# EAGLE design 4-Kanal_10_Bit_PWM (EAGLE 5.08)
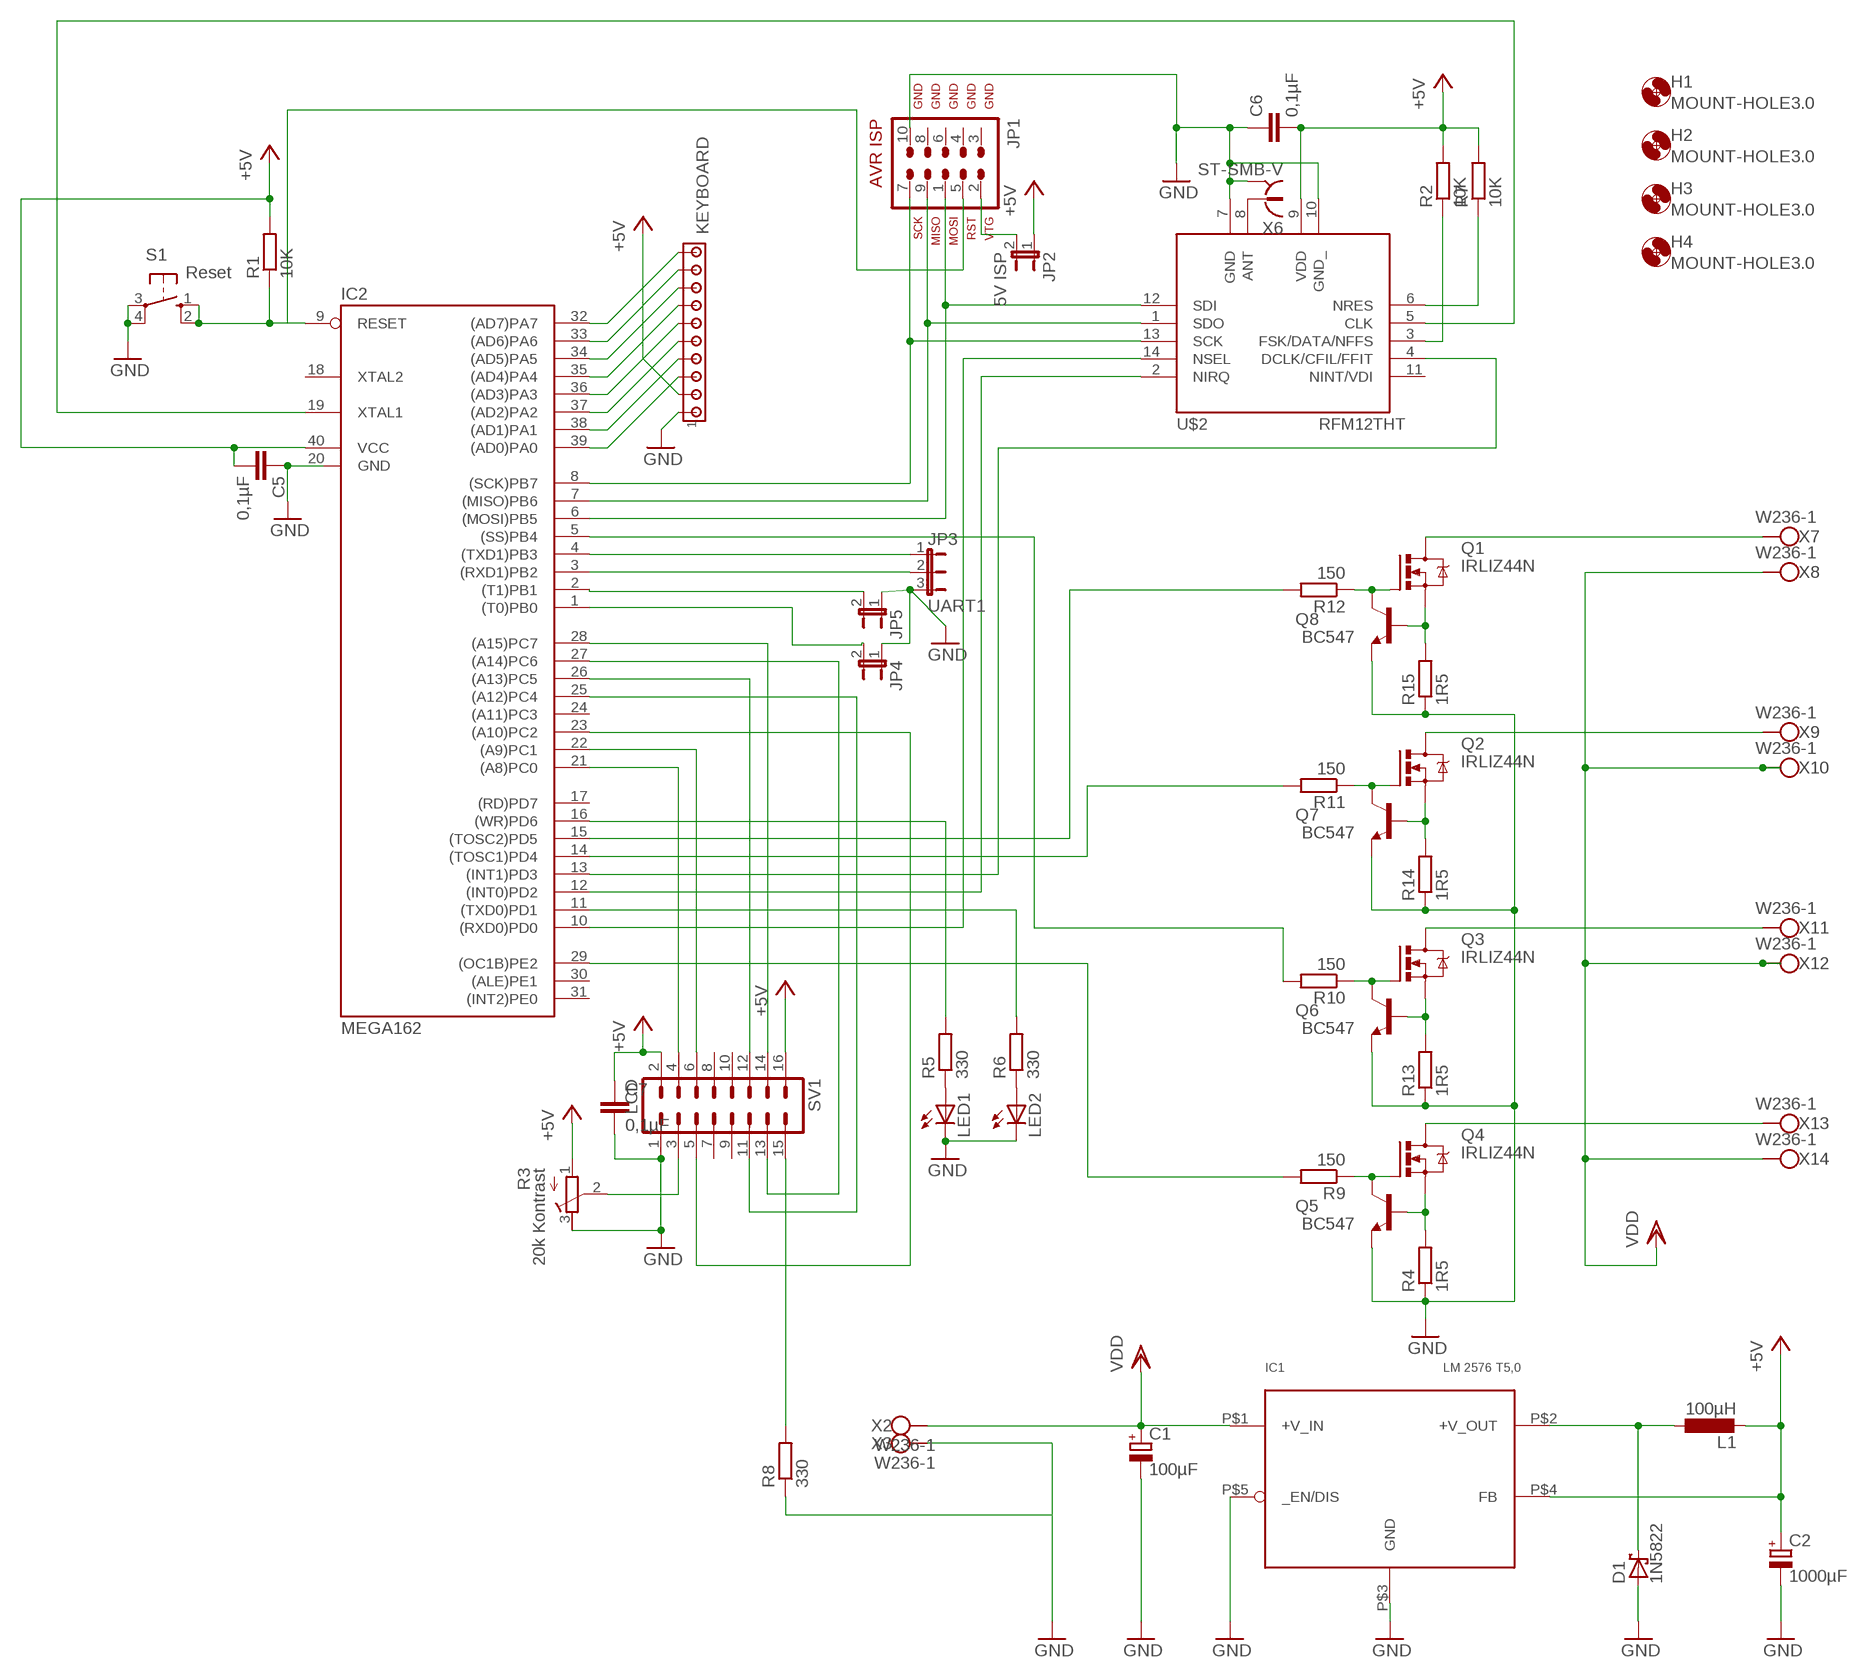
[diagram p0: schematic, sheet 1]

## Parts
C1  100µF  CPOL-EUE5-10.5  [E5-10,5]
C2  1000µF  CPOL-EUE5-10.5  [E5-10,5]
C5  0,1µF  C-EUC1812  [C1812]
C6  0,1µF  C-EUC1812  [C1812]
C7  0,1µF  C-EUC1812  [C1812]
D1  1N5822  1N5908  [C4111-15]
H1  MOUNT-HOLE3.0  [3,0]
H2  MOUNT-HOLE3.0  [3,0]
H3  MOUNT-HOLE3.0  [3,0]
H4  MOUNT-HOLE3.0  [3,0]
IC1  LM 2576 T5,0  LM2576-T05D  [TO220-5_STAGGERED]
IC2  MEGA162  MEGA161LP  [DIL40]
JP1  AVR-ISP  AVR-ISP-10ML10  [ML10]
JP2  5V ISP  JP1E  [JP1]
JP3  UART1  JP2E  [JP2]
JP4  JP1E  [JP1]
JP5  JP1E  [JP1]
KEYBOARD  MTA10-100  [10X10MTA]
L1  100µH  L-EUTJ4-U1  [TJ4-U1]
LED1  LED5MM  [LED5MM]
LED2  LED5MM  [LED5MM]
Q1  IRLIZ44N  STP5NA50  [TO220BV]
Q2  IRLIZ44N  STP5NA50  [TO220BV]
Q3  IRLIZ44N  STP5NA50  [TO220BV]
Q4  IRLIZ44N  STP5NA50  [TO220BV]
Q5  BC547  2N5088  [TO92]
Q6  BC547  2N5088  [TO92]
Q7  BC547  2N5088  [TO92]
Q8  BC547  2N5088  [TO92]
R1  10K  R-EU_0207/7  [0207/7]
R2  10K  R-EU_0207/10  [0207/10]
R3  20k Kontrast  R-TRIMM64W  [RTRIM64W]
R4  1R5  R-EU_0207/7  [0207/7]
R5  330  R-EU_0207/7  [0207/7]
R6  330  R-EU_0207/7  [0207/7]
R7  10K  R-EU_0207/7  [0207/7]
R8  330  R-EU_0207/7  [0207/7]
R9  150  R-EU_0207/7  [0207/7]
R10  150  R-EU_0207/7  [0207/7]
R11  150  R-EU_0207/7  [0207/7]
R12  150  R-EU_0207/7  [0207/7]
R13  1R5  R-EU_0207/7  [0207/7]
R14  1R5  R-EU_0207/7  [0207/7]
R15  1R5  R-EU_0207/7  [0207/7]
S1  Reset  10-XX  [B3F-10XX]
SV1  LCD  ML16  [ML16]
U$2  RFM12THT  [RFM12]
X2  W236-1  [W236-1]
X3  W236-1  [W236-1]
X6  ST-SMB-V  [ST-SMB-V]
X7  W236-1  [W236-1]
X8  W236-1  [W236-1]
X9  W236-1  [W236-1]
X10  W236-1  [W236-1]
X11  W236-1  [W236-1]
X12  W236-1  [W236-1]
X13  W236-1  [W236-1]
X14  W236-1  [W236-1]

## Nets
+5V: C2.+ C5.2 C6.2 C7.1 IC1.P$4(FB) IC2.40(VCC) JP2.1 KEYBOARD.2 L1.2 R1.2 R2.2 R3.1(E) R7.2 SV1.2 SV1.16 U$2.9(VDD)
GND: C1.- C2.- C5.1 C6.1 C7.2 D1.A IC1.P$3(GND) IC1.P$5(_EN/DIS) JP1.10 JP3.3 JP4.1 JP5.1 KEYBOARD.1 LED1.K(C) LED2.K(C) Q5.3(E) Q6.3(E) Q7.3(E) Q8.3(E) R3.3(A) R4.1 R8.1 R13.1 R14.1 R15.1 S1.3(P) S1.4(P1) SV1.1 U$2.7(GND) U$2.10(GND_) X3.1(KL1) X6.2(GND)
N$1: IC2.39((AD0)PA0) KEYBOARD.3
N$2: D1.C IC1.P$2(+V_OUT) L1.1
N$3: Q1.D X7.1(KL1)
N$4: IC2.5((SS)PB4) R10.2
N$5: IC2.29((OC1B)PE2) R9.2
N$6: IC2.14((TOSC1)PD4) R11.2
N$7: Q2.D X9.1(KL1)
N$8: Q3.D X11.1(KL1)
N$9: Q4.D X13.1(KL1)
N$10: IC2.9(RESET) JP1.5 R1.1 S1.1(S) S1.2(S1)
N$11: IC2.12((INT0)PD2) U$2.2(NIRQ)
N$12: Q4.G Q5.1(C) R9.1
N$13: Q3.G Q6.1(C) R10.1
N$15: Q1.G Q8.1(C) R12.1
N$16: IC2.13((INT1)PD3) U$2.4(DCLK/CFIL/FFIT)
N$17: IC2.6((MOSI)PB5) JP1.1 U$2.12(SDI)
N$18: IC2.7((MISO)PB6) JP1.9 U$2.1(SDO)
N$19: IC2.8((SCK)PB7) JP1.7 U$2.13(SCK)
N$20: IC2.38((AD1)PA1) KEYBOARD.4
N$21: IC2.19(XTAL1) U$2.5(CLK)
N$22: R2.1 U$2.3(FSK/DATA/NFFS)
N$23: IC2.37((AD2)PA2) KEYBOARD.5
N$24: IC2.10((RXD0)PD0) U$2.14(NSEL)
N$25: JP1.2 JP2.2
N$26: IC2.36((AD3)PA3) KEYBOARD.6
N$27: IC2.35((AD4)PA4) KEYBOARD.7
N$28: IC2.34((AD5)PA5) KEYBOARD.8
N$29: IC2.33((AD6)PA6) KEYBOARD.9
N$30: IC2.32((AD7)PA7) KEYBOARD.10
N$31: IC2.4((TXD1)PB3) JP3.1
N$32: R3.2(S) SV1.3
N$34: IC2.28((A15)PC7) SV1.14
N$35: IC2.26((A13)PC5) SV1.12
N$36: IC2.21((A8)PC0) SV1.4
N$37: IC2.22((A9)PC1) SV1.6
N$38: IC2.27((A14)PC6) SV1.13
N$39: IC2.25((A12)PC4) SV1.11
N$40: Q4.S Q5.2(B) R4.2
N$41: Q2.G Q7.1(C) R11.1
N$42: Q3.S Q6.2(B) R13.2
N$43: Q2.S Q7.2(B) R14.2
N$44: IC2.23((A10)PC2) SV1.5
N$45: U$2.8(ANT) X6.1
N$46: IC2.15((TOSC2)PD5) R12.2
N$47: LED1.A R5.1
N$48: IC2.16((WR)PD6) R5.2
N$49: IC2.3((RXD1)PB2) JP3.2
N$50: LED2.A R6.1
N$51: IC2.11((TXD0)PD1) R6.2
N$52: IC2.1((T0)PB0) JP4.2
N$53: IC2.2((T1)PB1) JP5.2
N$55: R7.1 U$2.6(NRES)
N$56: Q1.S Q8.2(B) R15.2
N$75: R8.2 SV1.15
VDD: C1.+ IC1.P$1(+V_IN) X2.1(KL1) X8.1(KL1) X10.1(KL1) X10.2(KL2) X12.1(KL1) X12.2(KL2) X14.1(KL1)
Unconnected: IC2.17((RD)PD7) IC2.18(XTAL2) IC2.24((A11)PC3) IC2.30((ALE)PE1) IC2.31((INT2)PE0) JP1.3 JP1.4 JP1.6 JP1.8 SV1.7 SV1.8 SV1.9 SV1.10 U$2.11(NINT/VDI) X2.2(KL2) X3.2(KL2) X7.2(KL2) X8.2(KL2) X9.2(KL2) X11.2(KL2) X13.2(KL2) X14.2(KL2)

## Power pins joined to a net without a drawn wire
GND: IC2.20(GND) X6.3(GND) X6.4(GND) X6.5(GND)

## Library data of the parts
C1 C2 = rcl:CPOL-EU: POLARIZED CAPACITOR, European symbol
C5-C7 = rcl:C-EU: CAPACITOR, European symbol
D1 = diode:1N5908: DIODE
H1-H4 = holes:MOUNT-HOLE: MOUNTING HOLE with drill center marker
IC1 = to220-custom:LM2576-T05D: LM2576/LM2576HV Series SIMPLE SWITCHER® 3A Step-Down Voltage Regulator STAGGERED PACKAGE
IC2 = atmel:MEGA161*P: MICROCONTROLLER 16 Kbytes FLASH 512 bytes EEPROM 1 Kbytes SRAM dual UART hardware multiplier Source: avr.lbr
JP1 = uwegw_eagle_lib:AVR-ISP-10: AVR ISP-10 Serial Programming Header
JP2 JP4 JP5 = jumper:JP1E: JUMPER
JP3 = jumper:JP2E: JUMPER
KEYBOARD = con-amp:MTA10-100: AMP connector
L1 = rcl:L-EU: INDUCTOR, European symbol
LED1 LED2 = led:LED: LED
Q1-Q4 = transistor-power:STP5NA50: N-CHANNEL MOS FET
Q5-Q8 = transistor-npn:2N5088: NPN Transistor
R1 R2 R4-R15 = rcl:R-EU_: RESISTOR, European symbol
R3 = rcl:R-TRIMM: Trimm resistor
S1 = switch-omron:10-XX: OMRON SWITCH
SV1 = con-harting-ml:ML16: HARTING
U$2 = uwegw_eagle_lib:RFM12: RFM12 Funkmodul SPI-Schnittstelle 433MHz Pollin Nr. 810049
X2 X3 X7-X14 = con-wago-508:W236-1: WAGO SREW CLAMP
X6 = con-coax:ST-SMB-V: MALE SMB CONNECTOR Radiall distributor RS 193-8855G7

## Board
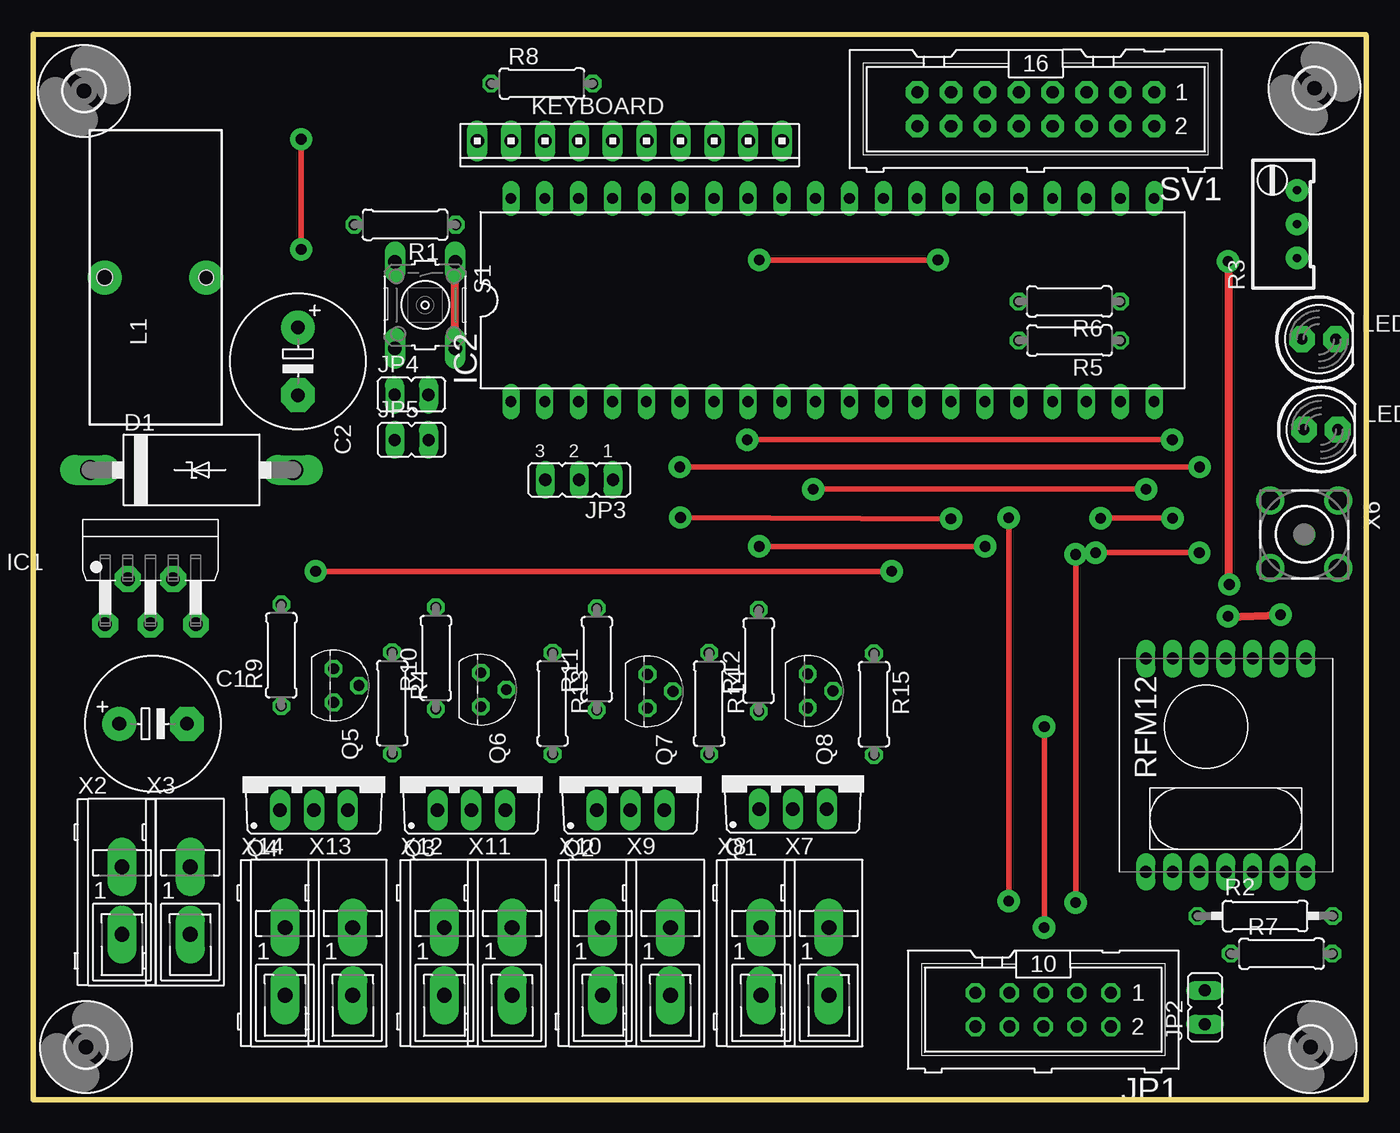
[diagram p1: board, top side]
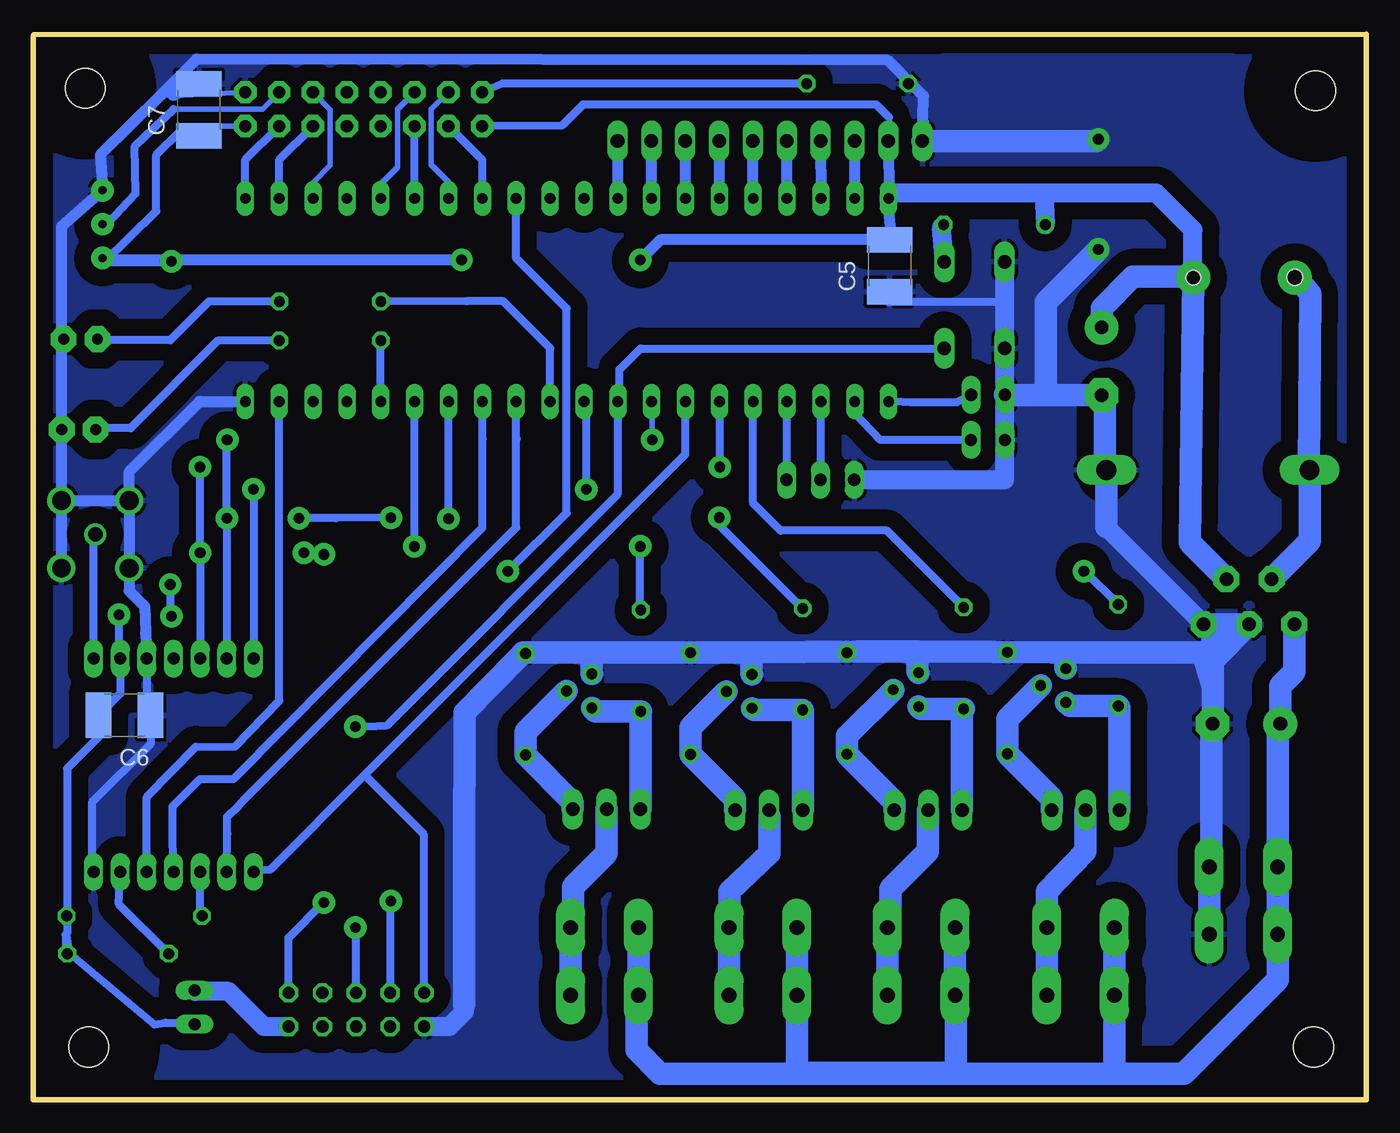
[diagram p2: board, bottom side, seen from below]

Size 100 x 80 mm. Coordinates in mm from the lower left corner, seen from the top.
Outline: 100,79.8 100,0 0,0 0,79.94
Outline: 0,80 0,79.94
Outline: 0,79.94 99.98,79.89
Copper layers (1*16): Top 0.035mm / dielectric 1.5mm / Bottom 0.035mm
Design rules "default": minimum track width 10mil, minimum drill 24mil, track to track 8mil, track to pad 8mil, pad to pad 8mil, via to via 8mil, smd to smd 8mil, copper to edge 40mil, drill to drill 8mil, minimum pad ring 10mil, minimum via ring 8mil, stop-mask expansion 4mil, vias tented up to drill 0mil, thermal gap 10mil

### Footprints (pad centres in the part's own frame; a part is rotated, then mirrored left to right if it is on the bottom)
E5-10,5 = drill 1.016 pad 2.54 round: + -2.54,0 | drill 1.016 pad 2.54 octagon: - 2.54,0
C1812 = smd 1.9 x 3.4: 1 -1.95,0; 2 1.95,0
C4111-15 = drill 1.499 long: A 7.62,0; C -7.62,0
3,0 = hole 3: 0,0
TO220-5_STAGGERED = drill 1.016 pad 1.93 octagon: P$1 -3.404,-3.404; P$2 -1.702,0; P$3 0,-3.404; P$4 1.702,0; P$5 3.404,-3.404
DIL40 = drill 0.813 long: 1 -24.13,-7.62; 2 -21.59,-7.62; 3 -19.05,-7.62; 4 -16.51,-7.62; 5 -13.97,-7.62; 6 -11.43,-7.62; 7 -8.89,-7.62; 8 -6.35,-7.62; 9 -3.81,-7.62; 10 -1.27,-7.62; 11 1.27,-7.62; 12 3.81,-7.62; 13 6.35,-7.62; 14 8.89,-7.62; 15 11.43,-7.62; 16 13.97,-7.62; 17 16.51,-7.62; 18 19.05,-7.62; 19 21.59,-7.62; 20 24.13,-7.62; 21 24.13,7.62; 22 21.59,7.62; 23 19.05,7.62; 24 16.51,7.62; 25 13.97,7.62; 26 11.43,7.62; 27 8.89,7.62; 28 6.35,7.62; 29 3.81,7.62; 30 1.27,7.62; 31 -1.27,7.62; 32 -3.81,7.62; 33 -6.35,7.62; 34 -8.89,7.62; 35 -11.43,7.62; 36 -13.97,7.62; 37 -16.51,7.62; 38 -19.05,7.62; 39 -21.59,7.62; 40 -24.13,7.62
ML10 = drill 0.914 octagon: 1 -5.08,-1.27; 2 -5.08,1.27; 3 -2.54,-1.27; 4 -2.54,1.27; 5 0,-1.27; 6 0,1.27; 7 2.54,-1.27; 8 2.54,1.27; 9 5.08,-1.27; 10 5.08,1.27
JP1 = drill 0.914 long: 1 0,-1.27; 2 0,1.27
JP2 = drill 0.914 long: 1 -2.54,0; 2 0,0; 3 2.54,0
10X10MTA = drill 1.016 long: 1 11.43,0; 2 8.89,0; 3 6.35,0; 4 3.81,0; 5 1.27,0; 6 -1.27,0; 7 -3.81,0; 8 -6.35,0; 9 -8.89,0; 10 -11.43,0
TJ4-U1 = drill 0.9 pad 2.54 round: 1 -3.808,0; 2 3.808,0 | hole 1.2: -3.81,0 | hole 1.1: 3.81,0
LED5MM = drill 0.813 pad 1.93 octagon: A -1.27,0; K 1.27,0
TO220BV = drill 1.016 long: D 0,-2.54; G -2.54,-2.54; S 2.54,-2.54
TO92 = drill 0.813 octagon: 1 1.27,0; 2 0,1.905; 3 -1.27,0
0207/7 = drill 0.813 octagon: 1 -3.81,0; 2 3.81,0
0207/10 = drill 0.813 octagon: 1 -5.08,0; 2 5.08,0
RTRIM64W = drill 0.61 pad 1.676 round: 1 1.27,-2.54; 2 1.27,0; 3 1.27,2.54
B3F-10XX = drill 1.016 long: 1 -3.251,2.261; 2 3.251,2.261; 3 -3.251,-2.261; 4 3.251,-2.261
ML16 = drill 0.914 pad 1.676 octagon: 1 -8.89,-1.27; 2 -8.89,1.27; 3 -6.35,-1.27; 4 -6.35,1.27; 5 -3.81,-1.27; 6 -3.81,1.27; 7 -1.27,-1.27; 8 -1.27,1.27; 9 1.27,-1.27; 10 1.27,1.27; 11 3.81,-1.27; 12 3.81,1.27; 13 6.35,-1.27; 14 6.35,1.27; 15 8.89,-1.27; 16 8.89,1.27
RFM12 = drill 0.9 long: 1 -8,6; 2 -8,4; 3 -8,2; 4 -8,0; 5 -8,-2; 6 -8,-4; 7 -8,-6; 8 8,-6; 9 8,-4; 10 8,-2; 11 8,0; 12 8,2; 13 8,4; 14 8,6
W236-1 = drill 1.118 pad 2.184 long: 1 0,-2.54; 2 0,2.54
ST-SMB-V = drill 1.1 round: 1 0,0 | drill 1.4 round: 2 -2.54,2.54; 3 2.54,2.54; 4 2.54,-2.54; 5 -2.54,-2.54

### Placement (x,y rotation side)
C1  8.98,28.2 0 top
C2  19.85,55.39 270 top
C5  35.76,62.56 90 bottom
C6  93.16,28.83 180 bottom
C7  87.57,74.26 90 bottom
D1  11.87,47.24 0 top
H1  3.94,3.94 0 top
H2  95.84,3.94 0 top
H3  96.11,75.88 0 top
H4  3.81,75.69 0 top
IC1  8.79,39.05 0 top
IC2  59.96,59.99 0 top
JP1  75.77,6.74 180 top
JP2  87.9,6.92 0 top
JP3  40.95,46.5 180 top
JP4  28.37,52.88 270 top
JP5  28.38,49.49 270 top
KEYBOARD  44.74,71.92 180 top
L1  9.17,61.68 0 top
LED1  96.6,50.27 0 top
LED2  96.46,57.05 0 top
Q1  56.99,24.33 0 top
Q2  44.8,24.26 0 top
Q3  32.86,24.26 0 top
Q4  21.05,24.26 0 top
Q5  22.52,31.06 270 top
Q6  33.58,30.75 270 top
Q7  46.08,30.63 270 top
Q8  58.1,30.66 270 top
R1  27.89,65.64 180 top
R2  92.42,13.77 0 top
R3  93.54,65.68 0 top
R4  26.92,29.75 270 top
R5  77.74,56.95 180 top
R6  77.73,59.88 180 top
R7  93.65,10.94 0 top
R8  38.16,76.23 0 top
R9  18.6,33.33 90 top
R10  30.2,33.12 90 top
R11  42.28,33.04 90 top
R12  54.42,32.93 90 top
R13  38.96,29.72 270 top
R14  50.7,29.71 270 top
R15  63.07,29.66 270 top
S1  29.4,59.61 270 top
SV1  75.21,74.31 180 top
U$2  89.48,25.08 90 top
X2  6.65,14.92 0 top
X3  11.77,14.92 0 top
X6  95.35,42.41 270 top
X7  59.68,10.36 0 top
X8  54.6,10.36 0 top
X9  47.8,10.36 0 top
X10  42.72,10.36 0 top
X11  35.92,10.36 0 top
X12  30.84,10.36 0 top
X13  23.97,10.36 0 top
X14  18.89,10.36 0 top

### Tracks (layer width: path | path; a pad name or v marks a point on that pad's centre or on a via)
+5V  (via drill 0.8 pad 1.68)
  Top 0.406: v54.47,62.99 v67.87,62.99
  Top 0.61: v89.64,62.89 89.64,38.73 v89.73,38.64 | v89.64,36.27 89.73,36.37 89.57,36.21 v93.58,36.37
  Bottom 0.406: R7.2 97.58,10.84 R2.2 | SV1.2 88.21,73.03 88.21,72.71 | 35.78,73.67 35.78,71.99 KEYBOARD.2 | 88.21,72.71 88.21,72.35 C7.1 | C6.2 95.11,27.19 | 88.01,5.76 JP2.1 | 13.59,61.73 13,62.32 | 97.42,11.08 97.17,10.74 97.47,12.48 97.58,12.37 | R3.1 94.68,62.84 94.53,62.99 | 88.95,72.71 88.21,72.71
  Bottom 0.61: 35.75,67.69 IC2.40 35.83,66.67 | 35.67,64.83 35.67,63.91 C5.2 | C6.2 93.48,30.46 U$2.9 93.58,33.18 v93.58,36.37 | SV1.16 60.35,73.08 58.76,74.65 36.76,74.65 35.78,73.67 | 95.11,27.19 97.47,24.83 97.47,12.48 | 88.01,5.76 90.07,5.76 90.92,5.63 97.42,11.08 | 97.58,12.37 97.58,10.84 | 88.95,72.71 90.77,70.89 90.77,66.65 94.68,62.84 89.69,62.84 v89.64,62.89 | v89.73,38.64 89.73,36.43 89.76,36.4 v89.64,36.27
  Bottom 0.813: 35.75,67.69 KEYBOARD.2 | 35.83,66.67 35.67,64.83 | v67.87,62.99 94.53,62.99 | v54.47,62.99 52.95,64.51 C5.2
  Bottom 1.422: 13,62.32 13,65.26 15.76,68.02 19.21,68.02 | 19.21,68.02 35.42,68.02 IC2.40 | R1.2 24.2,67.99 19.21,68.02
  Bottom 1.676: IC1.P$4 13.24,41.8 L1.2 13.15,61.73 13.59,61.73 17.5,61.73 19.85,59.38 C2.+
GND  (via drill 0.8 pad 1.68)
  Top 0.406: v20.09,63.78 v20.09,72.06
  Bottom 0.406: 90.39,75.38 89.53,75.33 SV1.1 | 91.48,29.1 C6.1 | 95.61,17.21 U$2.7 | JP1.10 70.59,5.37 | 87.41,76.46 C7.2 | 27.1,63.5 27.14,63.54 | S1.4 27.14,58.4 27.13,58.41 | LED2.K 97.89,56.88 | LED1.K 97.87,50.35 97.89,50.37 | X6.5 92.79,44.98
  Bottom 0.61: JP5.1 27.21,50.42 JP4.1 27.13,58.41 27.09,59.85 | 27.09,59.85 27.1,63.5 | KEYBOARD.1 33.07,73.34 | C5.1 35.78,59.83 27.09,59.85 | 33.93,76.01 34.68,76.17 34.09,76.07 R8.1 | U$2.10 91.48,29.1 | C6.1 91.21,26.69 95.61,22.29 95.61,17.21 | 27.14,63.54 S1.3
  Bottom 0.813: KEYBOARD.1 33.21,75.29 33.93,76.01 35.89,77.97 87.76,78.07 90.39,75.38 94.97,70.89 R3.3 97.89,65.5 97.89,56.88 97.89,50.37 X6.2 | U$2.10 91.58,35 91.63,36.99 92.81,38.17 X6.4 X6.5 X6.2 | X6.2 X6.3 | 89.53,75.33 87.41,76.46 | IC2.20 87.53,52.37 92.79,47.12 92.79,44.98 | 67.67,19.62 67.67,17.78 | R4.1 27.93,33.57 | R13.1 38.88,33.61 38.1,33.61 | R14.1 50.8,33.53 | R15.1 63.5,33.04 63.5,33.02 63.63,33.15
  Bottom 1.422: IC1.P$5 19.49,42.94 | JP1.10 68.8,5.47 67.67,6.6 67.67,19.62 | JP3.3 27.14,46.5 S1.3
  Bottom 1.676: 11.53,30.98 12.29,33.53 22.56,33.53 | 22.56,33.53 23.6,33.53 27.93,33.57 33.69,33.61 | 33.69,33.61 35.57,33.63 38.1,33.61 46.1,33.54 | 46.1,33.54 47.27,33.53 50.8,33.53 58.12,33.53 | 58.12,33.53 63.26,33.53 63.63,33.15 67.64,29.06 67.67,17.78 67.69,7.11 | X3.1 11.77,17.47 11.63,17.61 11.63,28.09 C1.- 11.53,30.98 | 11.53,30.98 11.53,32.91 IC1.P$3 IC1.P$5 11.54,34.99 11.54,33.46 | C2.- 24.03,52.86 | 24.03,52.86 27.07,52.85 JP4.1 | KEYBOARD.1 20.23,71.92 v20.09,72.06 | v20.09,63.78 24.03,59.84 24.03,52.86 | Q5.3 22.56,32.37 22.56,33.53 | Q6.3 33.69,32.12 33.69,33.61 | Q7.3 46.1,31.92 46.1,33.54 | Q8.3 58.12,31.95 58.12,33.53 | 19.49,42.94 D1.A
  pour Bottom (isolate 1.27): 100.21,80.1 100.21,-0.2 -0.39,-0.2 -0.12,80.17
N$1
  Bottom 0.61: 38.37,71.93 KEYBOARD.3
  Bottom 0.813: IC2.39 38.37,71.93
N$2
  Bottom 1.676: IC1.P$2 4.25,41.89 D1.C 4.3,47.29 4.21,60.46 5.22,61.66 L1.1
N$3
  Bottom 1.27: 59.68,12.95 59.52,13.11
  Bottom 1.676: X7.1 59.68,12.95 | 59.52,13.11 59.52,15.94 56.99,18.47 Q1.D
N$4
  Bottom 0.61: IC2.5 45.99,44.74 43.93,42.68 35.95,42.68 R10.2
N$5  (via drill 0.8 pad 1.68)
  Top 0.406: v21.18,39.63 v64.4,39.63
  Bottom 0.61: IC2.29 63.77,63.13 59.98,59.35 59.98,44 v64.4,39.63 | v21.18,39.63 21.09,39.63 R9.2
N$6  (via drill 0.8 pad 1.68)
  Top 0.406: v48.55,43.67 v68.85,43.57
  Bottom 0.61: v68.85,43.57 IC2.14 | v48.55,43.67 48.55,43.12 R11.2
N$7
  Bottom 1.27: 47.8,12.93 47.77,12.96 | 44.78,21.26 Q2.D
  Bottom 1.676: X9.1 47.8,12.93 | 47.77,12.96 47.77,15.63 44.78,18.46 44.78,21.26
N$8
  Bottom 1.27: 35.92,13.34 35.71,13.55 | 32.89,21.69 Q3.D
  Bottom 1.676: X11.1 35.92,13.34 | 35.71,13.55 35.71,15.8 32.89,18.62 32.89,21.69
N$9
  Bottom 1.27: 23.97,13.24 23.96,13.25 | 21.06,21.65 Q4.D
  Bottom 1.676: X13.1 23.97,13.24 | 23.96,13.25 23.96,15.63 21.06,18.61 21.06,21.65
N$10  (via drill 0.8 pad 1.68)
  Top 0.406: v75.85,27.97 75.87,27.91 75.85,22.93 v75.84,12.91
  Top 0.61: S1.2 S1.1
  Bottom 0.406: 31.86,65.46 R1.1 | IC2.9 56.02,52.5 | 75.77,13.04 v75.84,12.91
  Bottom 0.61: S1.2 54.44,56.36 56.02,54.78 56.02,52.5 | IC2.9 56.15,45.45 73.44,28.07 v75.85,27.97 | JP1.5 75.77,13.04
  Bottom 1.422: S1.1 31.86,65.46
N$11
  Bottom 0.61: 63.77,49.61 IC2.12 | 63.77,49.61 63.74,49.58 | 63.77,49.61 63.77,42.91 84.14,22.55 84.61,22.05 85.46,21.21 85.45,19.95 U$2.2
N$12
  Bottom 1.676: Q5.1 22.25,29.52 R9.1 18.51,29.43 Q4.G
N$13
  Bottom 1.676: Q6.1 33.41,29.31 R10.1 30.32,29.19 Q3.G
N$15
  Bottom 1.676: Q8.1 57.83,29.12 R12.1 54.45,29.09 Q1.G
N$16
  Bottom 0.61: 66.31,49.61 IC2.13 | 66.31,49.61 66.28,49.58 | 66.31,49.61 66.31,42.91 84.97,24.05 87.49,24.05 89.55,21.99 89.55,19.45 U$2.4
N$17  (via drill 0.8 pad 1.68)
  Top 0.406: v87.5,47.46 v48.49,47.46 | v78.21,14.78 v78.21,40.9 | v79.69,41.03 v87.48,41.03
  Bottom 0.406: 87.48,47.47 v87.5,47.46 | 48.49,52.33 IC2.6 | v78.21,40.9 v79.69,41.03
  Bottom 0.61: U$2.12 v87.48,41.03 87.48,47.47 | v48.49,47.46 48.49,52.33 | JP1.1 80.85,12.14 v78.21,14.78
N$18
  Bottom 0.406: 83.32,17.15 U$2.1 83.29,16.89
  Bottom 0.61: IC2.7 51.07,48.43 75.16,24.34 | 75.16,24.34 82.25,17.25 83.41,17.15 U$2.1 | JP1.9 70.69,19.88 75.16,24.34
N$19  (via drill 0.8 pad 1.68)
  Top 0.406: v85.45,49.51 v53.57,49.51 | v73.18,14.88 v73.18,43.66 | v80.08,43.62 v85.48,43.62
  Bottom 0.406: 85.48,49.48 v85.45,49.51 | v53.57,49.51 53.57,52.33 IC2.8 | JP1.7 73.18,8.06
  Bottom 0.61: U$2.13 v85.48,43.62 85.48,49.48 | 73.18,8.06 v73.18,14.88 | v73.18,43.66 77.3,43.62 v80.08,43.62
N$20
  Bottom 0.61: IC2.38 40.83,67.69
  Bottom 0.813: 40.83,67.69 KEYBOARD.4
N$21
  Bottom 0.406: 81.54,52.48 IC2.19
  Bottom 0.61: U$2.5 91.48,22.7 87.81,26.47 84.87,26.49 81.54,29.92 81.54,52.48
N$22
  Bottom 0.406: R2.1 87.48,14.06
  Bottom 0.61: 87.48,14.06 U$2.3
N$23
  Bottom 0.61: 43.45,71.73 KEYBOARD.5
  Bottom 0.813: IC2.37 43.45,71.73
N$24  (via drill 0.8 pad 1.68)
  Top 0.406: v58.51,45.79 v83.49,45.79
  Bottom 0.406: v83.49,45.79 v83.48,45.78 | 58.51,52.54 IC2.10
  Bottom 0.61: v83.48,45.78 U$2.14 | v58.51,45.79 58.51,52.54
N$25
  Bottom 1.422: JP1.2 82.7,5.47 85.34,8.11 87.82,8.11 JP2.2
N$26
  Bottom 0.61: 45.99,72.03 KEYBOARD.6
  Bottom 0.813: IC2.36 45.99,72.03
N$27
  Bottom 0.61: 48.53,71.54 KEYBOARD.7
  Bottom 0.813: IC2.35 48.53,71.54
N$28
  Bottom 0.61: 51.07,70.56 KEYBOARD.8
  Bottom 0.813: IC2.34 51.07,70.56
N$29
  Bottom 0.61: 53.61,71.54 KEYBOARD.9
  Bottom 0.813: IC2.33 53.61,71.54
N$30
  Bottom 0.61: 56.15,71.05 KEYBOARD.10
  Bottom 0.813: IC2.32 56.15,71.05
N$31
  Bottom 0.61: IC2.4 43.45,47.43 JP3.1
N$32
  Bottom 0.406: 94.43,65.74 R3.2 | 89.48,74.31 82.78,74.31 SV1.3
  Bottom 0.61: 94.43,65.74 92.34,67.96 92.43,71.49 89.48,74.31
N$34
  Bottom 0.61: IC2.28 66.31,70.49 SV1.14
N$35
  Bottom 0.406: SV1.12
  Bottom 0.61: IC2.26 SV1.12
N$36
  Bottom 0.61: SV1.4 84.09,70.51 IC2.21
N$37
  Bottom 0.61: SV1.6 81.55,70.51 IC2.22
N$38
  Bottom 0.406: SV1.13 70.15,74.29 70.15,70.14 68.85,68.84 IC2.27
N$39
  Bottom 0.406: SV1.11 72.66,74.32 72.66,69.95 73.93,68.68 IC2.25
N$40
  Bottom 1.676: Q4.S 23.59,22.61 R4.2 26.92,28.57 Q5.2
N$41
  Bottom 1.676: Q7.1 45.95,29.23 R11.1 42.26,29.21 Q2.G
N$42
  Bottom 1.676: Q3.S 35.4,22.35 R13.2 38.96,27.27 Q6.2
N$43
  Bottom 1.676: Q2.S 47.34,22.54 R14.2 50.7,27.91 Q7.2
N$44
  Bottom 0.406: SV1.5 77.72,74.28 77.72,70.09 79.01,68.8 IC2.23
N$45
  Bottom 0.406: 95.48,42.28 X6.1
  Bottom 0.61: U$2.8 95.48,42.28
N$46  (via drill 0.8 pad 1.68)
  Top 0.406: v54.47,41.5 v71.41,41.5
  Bottom 0.406: 71.41,52.37 IC2.15
  Bottom 0.61: v71.41,41.5 71.41,52.37 | v54.47,41.5 54.47,36.79 R12.2
N$47
  Bottom 0.406: 95.23,50.37 LED1.A
  Bottom 0.61: R5.1 86.17,56.94 92.69,50.37 95.23,50.37
N$48
  Bottom 0.61: IC2.16 R5.2
N$49
  Bottom 0.61: IC2.3 40.91,47.53 JP3.2
N$50
  Bottom 0.406: 95.12,56.98 LED2.A
  Bottom 0.61: R6.1 86.83,59.88 89.73,56.98 95.12,56.98
N$51
  Bottom 0.61: IC2.11 61.23,56.38 64.74,59.89 67.48,59.89 R6.2
N$52
  Bottom 0.61: IC2.1 35.83,52.39 34.19,52.31 30.74,52.31 JP4.2
N$53
  Bottom 0.61: IC2.2 38.37,51.51 36.45,49.49 JP5.2
N$54
  Bottom 1.676: 19.59,46.92 19.59,52.65 19.42,52.82
N$55
  Bottom 0.61: U$2.6 93.58,14.65 R7.1
N$56
  Bottom 1.676: Q1.S 59.53,22.31 R15.2 63.07,27.59 Q8.2
N$57
  pour Bottom: 9.95,78.35 31.86,78.35 31.66,73.66 9.95,73.56
N$75
  Bottom 0.61: R8.2 64.8,76.23 SV1.15
VDD
  Bottom 0.61: X10.1 42.72,3 43.18,2.54 30.91,2.54 30.83,2.46 X12.1
  Bottom 1.27: 54.76,7.66 X8.1 | 54.6,13.24 54.61,13.25 | 42.71,7.74 42.72,7.75 | 42.56,1.94 42.71,2.09 | 30.8,7.6 30.84,7.64 | X14.1 18.89,12.8 18.9,12.81 | 18.9,2.68 19.05,2.53 19.05,1.94
  Bottom 1.676: 30.8,1.94 19.05,1.94 13.69,1.94 6.65,8.98 X2.1 6.65,27.99 C1.+ 6.45,31.02 5.38,32.09 IC1.P$1 | 30.8,1.94 42.56,1.94 52.98,1.94 54.76,3.72 54.76,7.66 | X8.1 54.6,13.24 | 42.72,7.75 X10.1 X10.2 | 42.71,2.09 42.71,7.74 | 30.84,7.64 X12.1 X12.2 | 30.8,1.94 30.8,7.6 | 18.9,2.68 18.9,12.81

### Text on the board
bRestrict: ESMax_R_KSQ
